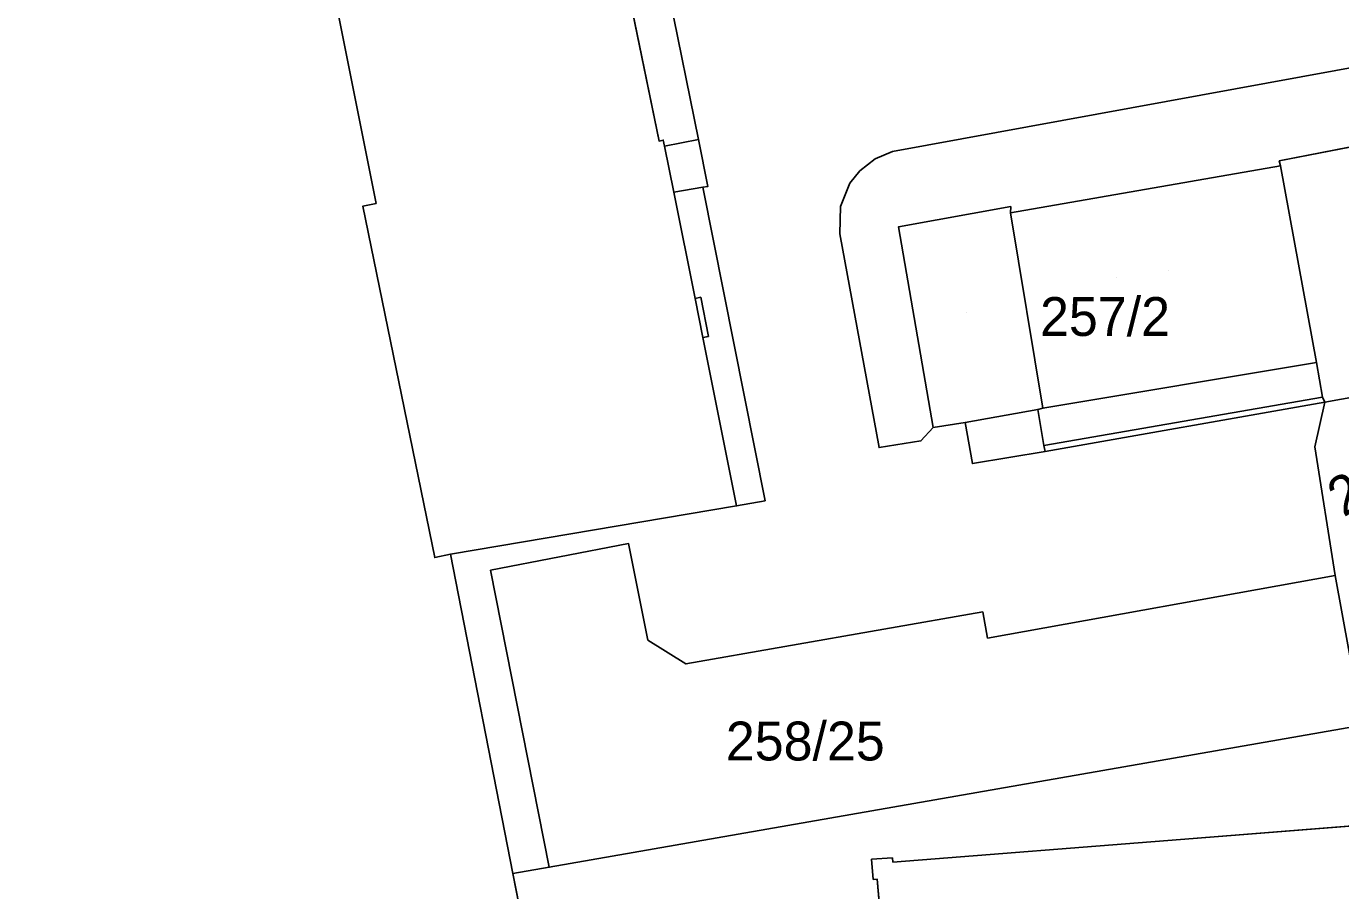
# Model space of a CAD drawing. Extents: x -263423 to -261326, y -1240067 to -1237864.
# Drawn here: x -263422.7 to -263355, y -1239493.9 to -1239449.5 of the extents above; entities that cross this region are included whole.
import ezdxf

# ---------------------------------------------------------------- set-up
doc = ezdxf.new("R2010")
doc.units = 0
for name, color, linetype in [('body_kn', 7, 'Continuous'), ('katuz_linie', 7, 'Continuous'), ('kladpar_druhypozemkov', 7, 'Continuous'), ('kladpar_hranice', 7, 'Continuous'), ('kladpar_parcelnecisla', 7, 'Continuous'), ('kladpar_plochy', 7, 'Continuous'), ('linie', 7, 'Continuous'), ('zappar_hrandruhpozemk', 7, 'Continuous'), ('znacky', 7, 'Continuous'), ('zuob_linie', 7, 'Continuous'), ('zuob_plochy', 7, 'Continuous')]:
    doc.layers.add(name, color=color, linetype=linetype)

msp = doc.modelspace()

# ---------------------------------------------------------------- linework, layer by layer
at = {"layer": 'body_kn'}
for p, q in [((-263390.09, -1239455.38), (-263390.09, -1239455.38)), ((-263389.88, -1239455.33), (-263389.88, -1239455.33)), ((-263389.82, -1239455.64), (-263389.82, -1239455.64)), ((-263388.07, -1239455.31), (-263388.07, -1239455.31)), ((-263378.96, -1239456.29), (-263378.96, -1239456.29)), ((-263378.08, -1239455.92), (-263378.08, -1239455.92)), ((-263358.16, -1239456.4), (-263358.16, -1239456.4)), ((-263379.75, -1239456.91), (-263379.75, -1239456.91)), ((-263358.1, -1239456.65), (-263358.1, -1239456.65)), ((-263358.1, -1239456.65), (-263358.1, -1239456.65)), ((-263387.84, -1239457.76), (-263387.84, -1239457.76)), ((-263387.84, -1239457.76), (-263387.84, -1239457.76)), ((-263387.58, -1239457.72), (-263387.58, -1239457.72)), ((-263380.27, -1239457.55), (-263380.27, -1239457.55)), ((-263404.66, -1239458.59), (-263404.66, -1239458.59)), ((-263389.34, -1239458.01), (-263389.34, -1239458.01)), ((-263389.34, -1239458.01), (-263389.34, -1239458.01)), ((-263405.35, -1239458.74), (-263405.35, -1239458.74)), ((-263380.75, -1239458.75), (-263380.75, -1239458.75)), ((-263372, -1239459.07), (-263372, -1239459.07)), ((-263372, -1239459.07), (-263372, -1239459.07)), ((-263371.99, -1239458.75), (-263371.99, -1239458.75)), ((-263377.77, -1239459.8), (-263377.77, -1239459.8)), ((-263380.78, -1239460.15), (-263380.78, -1239460.15)), ((-263388.24, -1239463.48), (-263388.24, -1239463.48)), ((-263387.95, -1239463.42), (-263387.95, -1239463.42)), ((-263387.84, -1239465.49), (-263387.84, -1239465.49)), ((-263387.84, -1239465.49), (-263387.84, -1239465.49)), ((-263387.55, -1239465.43), (-263387.55, -1239465.43)), ((-263356.25, -1239466.78), (-263356.25, -1239466.78)), ((-263356.25, -1239466.78), (-263356.25, -1239466.78)), ((-263355.94, -1239468.56), (-263355.94, -1239468.56)), ((-263355.94, -1239468.56), (-263355.94, -1239468.56)), ((-263370.59, -1239469.19), (-263370.59, -1239469.19)), ((-263370.33, -1239469.13), (-263370.33, -1239469.13)), ((-263370.33, -1239469.13), (-263370.33, -1239469.13)), ((-263355.82, -1239468.82), (-263355.82, -1239468.82)), ((-263374.33, -1239469.87), (-263374.33, -1239469.87)), ((-263374.33, -1239469.87), (-263374.33, -1239469.87)), ((-263375.98, -1239470.12), (-263375.98, -1239470.12)), ((-263378.77, -1239471.15), (-263378.77, -1239471.15)), ((-263376.61, -1239470.81), (-263376.61, -1239470.81)), ((-263370.28, -1239471.04), (-263370.28, -1239471.04)), ((-263370.22, -1239471.36), (-263370.22, -1239471.36)), ((-263356.33, -1239471.11), (-263356.33, -1239471.11)), ((-263373.96, -1239471.98), (-263373.96, -1239471.98)), ((-263386.1, -1239474.15), (-263386.1, -1239474.15)), ((-263384.63, -1239473.9), (-263384.63, -1239473.9)), ((-263391.66, -1239476.09), (-263391.66, -1239476.09)), ((-263401.64, -1239476.81), (-263401.64, -1239476.81)), ((-263400.83, -1239476.63), (-263400.83, -1239476.63)), ((-263398.77, -1239477.46), (-263398.77, -1239477.46)), ((-263355.29, -1239477.73), (-263355.29, -1239477.73)), ((-263373.43, -1239479.61), (-263373.43, -1239479.61)), ((-263390.67, -1239481.06), (-263390.67, -1239481.06)), ((-263373.18, -1239480.95), (-263373.18, -1239480.95)), ((-263388.71, -1239482.28), (-263388.71, -1239482.28)), ((-263363.24, -1239491.32), (-263363.24, -1239491.32)), ((-263379.15, -1239492.33), (-263379.15, -1239492.33)), ((-263378.08, -1239492.26), (-263378.08, -1239492.26)), ((-263397.62, -1239493.07), (-263397.62, -1239493.07)), ((-263395.75, -1239492.74), (-263395.75, -1239492.74)), ((-263378.05, -1239492.48), (-263378.05, -1239492.48)), ((-263379.07, -1239493.37), (-263379.07, -1239493.37)), ((-263378.86, -1239493.36), (-263378.86, -1239493.36))]:
    msp.add_line(p, q, dxfattribs=at)
at = {"layer": 'katuz_linie'}
msp.add_lwpolyline([(-263379.33, -1239586.34), (-263383.02, -1239567.53), (-263388.7, -1239538.56), (-263389.91, -1239532.38), (-263397.62, -1239493.07), (-263400.83, -1239476.63), (-263401.64, -1239476.81), (-263405.35, -1239458.74), (-263404.66, -1239458.59), (-263418.09, -1239391.46), (-263418.77, -1239388.14), (-263418.82, -1239387.92), (-263419.23, -1239385.88), (-263421.34, -1239375.54), (-263421.9, -1239372.78), (-263421.92, -1239372.66), (-263422.15, -1239371.54), (-263422.63, -1239368.77), (-263422.67, -1239368.54), (-263422.53, -1239349.75), (-263421.06, -1239264.03)], dxfattribs=at)
at = {"layer": 'kladpar_druhypozemkov'}
for p, q in [((-263366.56, -1239462.41), (-263366.56, -1239462.41)), ((-263374.26, -1239464.22), (-263374.26, -1239464.22)), ((-263381.83, -1239485.6), (-263381.83, -1239485.6))]:
    msp.add_line(p, q, dxfattribs=at)
at = {"layer": 'kladpar_hranice'}
for points in [[(-263396.18, -1239425.85), (-263390.09, -1239455.38), (-263389.88, -1239455.33), (-263389.82, -1239455.64), (-263388.07, -1239455.31), (-263387.58, -1239457.72), (-263387.84, -1239457.76), (-263389.34, -1239458.01), (-263388.24, -1239463.48), (-263387.95, -1239463.42), (-263387.55, -1239465.43), (-263387.84, -1239465.49), (-263386.1, -1239474.15), (-263400.83, -1239476.63), (-263401.64, -1239476.81), (-263405.35, -1239458.74), (-263404.66, -1239458.59), (-263418.09, -1239391.46)], [(-263345.41, -1239453.92), (-263358.16, -1239456.4), (-263358.1, -1239456.65), (-263372, -1239459.07), (-263371.99, -1239458.75), (-263377.77, -1239459.8), (-263375.98, -1239470.12), (-263374.33, -1239469.87), (-263373.96, -1239471.98), (-263370.22, -1239471.36), (-263355.82, -1239468.82), (-263356.33, -1239471.11), (-263355.29, -1239477.73), (-263373.18, -1239480.95), (-263373.43, -1239479.61), (-263388.71, -1239482.28), (-263390.67, -1239481.06), (-263391.66, -1239476.09), (-263398.77, -1239477.46), (-263395.75, -1239492.74), (-263397.62, -1239493.07), (-263400.83, -1239476.63), (-263386.1, -1239474.15), (-263387.84, -1239465.49), (-263387.55, -1239465.43), (-263387.95, -1239463.42), (-263388.24, -1239463.48), (-263389.34, -1239458.01), (-263387.84, -1239457.76), (-263387.58, -1239457.72), (-263388.07, -1239455.31), (-263389.82, -1239455.64), (-263389.88, -1239455.33), (-263390.09, -1239455.38), (-263396.18, -1239425.85)], [(-263345.41, -1239453.92), (-263346.15, -1239450.09), (-263306.88, -1239443.09), (-263306.58, -1239444.63), (-263305.83, -1239448.66), (-263303.99, -1239459.58), (-263329.55, -1239464.11), (-263329.37, -1239465.32), (-263332.48, -1239465.94), (-263332.42, -1239466.38), (-263335.14, -1239466.88), (-263335.27, -1239466.43), (-263338.25, -1239466.93), (-263338.5, -1239465.72), (-263342.75, -1239466.46), (-263355.82, -1239468.82), (-263355.94, -1239468.56), (-263356.25, -1239466.78), (-263358.1, -1239456.65), (-263358.16, -1239456.4), (-263345.41, -1239453.92)], [(-263358.1, -1239456.65), (-263356.25, -1239466.78), (-263355.94, -1239468.56), (-263355.82, -1239468.82), (-263370.22, -1239471.36), (-263373.96, -1239471.98), (-263374.33, -1239469.87), (-263375.98, -1239470.12), (-263377.77, -1239459.8), (-263371.99, -1239458.75), (-263372, -1239459.07), (-263358.1, -1239456.65)], [(-263389.91, -1239532.38), (-263397.62, -1239493.07), (-263395.75, -1239492.74), (-263353.87, -1239485.43), (-263325.89, -1239479.84), (-263317.64, -1239478.22), (-263315.49, -1239477.79), (-263315.85, -1239475.77), (-263316.6, -1239471.55), (-263269.27, -1239463.69), (-263264.52, -1239462.82)], [(-263269.27, -1239463.69), (-263316.6, -1239471.55), (-263315.85, -1239475.77), (-263315.49, -1239477.79), (-263317.64, -1239478.22), (-263325.89, -1239479.84), (-263353.87, -1239485.43), (-263355.29, -1239477.73), (-263356.33, -1239471.11), (-263355.82, -1239468.82), (-263342.75, -1239466.46)], [(-263353.87, -1239485.43), (-263395.75, -1239492.74), (-263398.77, -1239477.46), (-263391.66, -1239476.09), (-263390.67, -1239481.06), (-263388.71, -1239482.28), (-263373.43, -1239479.61), (-263373.18, -1239480.95), (-263355.29, -1239477.73), (-263353.87, -1239485.43)], [(-263314.18, -1239507.56), (-263316.62, -1239484.13), (-263327.94, -1239485.31), (-263327.33, -1239490.87), (-263328.05, -1239490.95), (-263327.76, -1239493.49), (-263331.17, -1239493.82), (-263331.7, -1239488.83), (-263346.85, -1239490.02), (-263363.24, -1239491.32), (-263378.05, -1239492.48), (-263378.08, -1239492.26), (-263379.15, -1239492.33), (-263379.07, -1239493.37), (-263378.86, -1239493.36), (-263378.5, -1239497.54)], [(-263363.24, -1239491.32), (-263346.85, -1239490.02), (-263331.7, -1239488.83), (-263331.17, -1239493.82), (-263327.76, -1239493.49), (-263327.58, -1239495.01), (-263329.16, -1239495.18), (-263328.74, -1239499.31), (-263327.1, -1239499.14), (-263327.04, -1239499.68), (-263328.76, -1239499.85), (-263334.62, -1239500.33), (-263335.83, -1239501.02), (-263336.28, -1239502.03), (-263336.11, -1239503.13), (-263335.45, -1239503.9)], [(-263378.5, -1239497.54), (-263378.86, -1239493.36), (-263379.07, -1239493.37), (-263379.15, -1239492.33), (-263378.08, -1239492.26), (-263378.05, -1239492.48), (-263363.24, -1239491.32)]]:
    msp.add_lwpolyline(points, dxfattribs=at)
at = {"layer": 'kladpar_plochy'}
for p, q in [((-263404.66, -1239458.59), (-263418.09, -1239391.46)), ((-263390.09, -1239455.38), (-263396.18, -1239425.85)), ((-263396.18, -1239425.85), (-263390.09, -1239455.38)), ((-263345.41, -1239453.92), (-263358.16, -1239456.4)), ((-263389.88, -1239455.33), (-263390.09, -1239455.38)), ((-263390.09, -1239455.38), (-263389.88, -1239455.33)), ((-263389.82, -1239455.64), (-263389.88, -1239455.33)), ((-263389.88, -1239455.33), (-263389.82, -1239455.64)), ((-263388.07, -1239455.31), (-263389.82, -1239455.64)), ((-263389.82, -1239455.64), (-263388.07, -1239455.31)), ((-263387.58, -1239457.72), (-263388.07, -1239455.31)), ((-263388.07, -1239455.31), (-263387.58, -1239457.72)), ((-263358.16, -1239456.4), (-263358.1, -1239456.65)), ((-263358.1, -1239456.65), (-263372, -1239459.07)), ((-263389.34, -1239458.01), (-263387.84, -1239457.76)), ((-263387.84, -1239457.76), (-263389.34, -1239458.01)), ((-263387.84, -1239457.76), (-263387.58, -1239457.72)), ((-263387.58, -1239457.72), (-263387.84, -1239457.76)), ((-263405.35, -1239458.74), (-263404.66, -1239458.59)), ((-263388.24, -1239463.48), (-263389.34, -1239458.01)), ((-263389.34, -1239458.01), (-263388.24, -1239463.48)), ((-263401.64, -1239476.81), (-263405.35, -1239458.74)), ((-263371.99, -1239458.75), (-263377.77, -1239459.8)), ((-263372, -1239459.07), (-263371.99, -1239458.75)), ((-263377.77, -1239459.8), (-263375.98, -1239470.12)), ((-263387.95, -1239463.42), (-263388.24, -1239463.48)), ((-263388.24, -1239463.48), (-263387.95, -1239463.42)), ((-263387.55, -1239465.43), (-263387.95, -1239463.42)), ((-263387.95, -1239463.42), (-263387.55, -1239465.43)), ((-263387.84, -1239465.49), (-263387.55, -1239465.43)), ((-263387.55, -1239465.43), (-263387.84, -1239465.49)), ((-263386.1, -1239474.15), (-263387.84, -1239465.49)), ((-263387.84, -1239465.49), (-263386.1, -1239474.15)), ((-263370.22, -1239471.36), (-263355.82, -1239468.82)), ((-263355.82, -1239468.82), (-263356.33, -1239471.11)), ((-263375.98, -1239470.12), (-263374.33, -1239469.87)), ((-263374.33, -1239469.87), (-263373.96, -1239471.98)), ((-263373.96, -1239471.98), (-263370.22, -1239471.36)), ((-263356.33, -1239471.11), (-263355.29, -1239477.73)), ((-263400.83, -1239476.63), (-263386.1, -1239474.15)), ((-263386.1, -1239474.15), (-263400.83, -1239476.63)), ((-263391.66, -1239476.09), (-263398.77, -1239477.46)), ((-263390.67, -1239481.06), (-263391.66, -1239476.09)), ((-263400.83, -1239476.63), (-263401.64, -1239476.81)), ((-263397.62, -1239493.07), (-263400.83, -1239476.63)), ((-263398.77, -1239477.46), (-263395.75, -1239492.74)), ((-263355.29, -1239477.73), (-263373.18, -1239480.95)), ((-263373.43, -1239479.61), (-263388.71, -1239482.28)), ((-263373.18, -1239480.95), (-263373.43, -1239479.61)), ((-263388.71, -1239482.28), (-263390.67, -1239481.06)), ((-263395.75, -1239492.74), (-263353.87, -1239485.43)), ((-263346.85, -1239490.02), (-263363.24, -1239491.32)), ((-263363.24, -1239491.32), (-263346.85, -1239490.02)), ((-263363.24, -1239491.32), (-263378.05, -1239492.48)), ((-263378.05, -1239492.48), (-263363.24, -1239491.32)), ((-263378.08, -1239492.26), (-263379.15, -1239492.33)), ((-263379.15, -1239492.33), (-263378.08, -1239492.26)), ((-263379.15, -1239492.33), (-263379.07, -1239493.37)), ((-263379.07, -1239493.37), (-263379.15, -1239492.33)), ((-263378.05, -1239492.48), (-263378.08, -1239492.26)), ((-263378.08, -1239492.26), (-263378.05, -1239492.48)), ((-263397.62, -1239493.07), (-263395.75, -1239492.74)), ((-263395.75, -1239492.74), (-263397.62, -1239493.07)), ((-263389.91, -1239532.38), (-263397.62, -1239493.07)), ((-263379.07, -1239493.37), (-263378.86, -1239493.36)), ((-263378.86, -1239493.36), (-263379.07, -1239493.37)), ((-263378.86, -1239493.36), (-263378.5, -1239497.54)), ((-263378.5, -1239497.54), (-263378.86, -1239493.36))]:
    msp.add_line(p, q, dxfattribs=at)
for points in [[(-263345.41, -1239453.92), (-263346.15, -1239450.09), (-263306.88, -1239443.09), (-263306.58, -1239444.63), (-263305.83, -1239448.66), (-263303.99, -1239459.58), (-263329.55, -1239464.11), (-263329.37, -1239465.32), (-263332.48, -1239465.94), (-263332.42, -1239466.38), (-263335.14, -1239466.88), (-263335.27, -1239466.43), (-263338.25, -1239466.93), (-263338.5, -1239465.72), (-263342.75, -1239466.46), (-263355.82, -1239468.82), (-263355.94, -1239468.56), (-263356.25, -1239466.78), (-263358.1, -1239456.65), (-263358.16, -1239456.4)], [(-263358.1, -1239456.65), (-263356.25, -1239466.78), (-263355.94, -1239468.56), (-263355.82, -1239468.82), (-263370.22, -1239471.36), (-263373.96, -1239471.98), (-263374.33, -1239469.87), (-263375.98, -1239470.12), (-263377.77, -1239459.8), (-263371.99, -1239458.75), (-263372, -1239459.07)], [(-263353.87, -1239485.43), (-263395.75, -1239492.74), (-263398.77, -1239477.46), (-263391.66, -1239476.09), (-263390.67, -1239481.06), (-263388.71, -1239482.28), (-263373.43, -1239479.61), (-263373.18, -1239480.95), (-263355.29, -1239477.73)]]:
    msp.add_lwpolyline(points, close=True, dxfattribs=at)
msp.add_lwpolyline([(-263353.87, -1239485.43), (-263355.29, -1239477.73), (-263356.33, -1239471.11), (-263355.82, -1239468.82), (-263342.75, -1239466.46)], dxfattribs=at)
at = {"layer": 'linie'}
msp.add_lwpolyline([(-263379.33, -1239586.34), (-263383.02, -1239567.53), (-263388.7, -1239538.56), (-263389.91, -1239532.38), (-263397.62, -1239493.07), (-263400.83, -1239476.63), (-263401.64, -1239476.81), (-263405.35, -1239458.74), (-263404.66, -1239458.59), (-263418.09, -1239391.46), (-263418.77, -1239388.14), (-263418.82, -1239387.92), (-263419.23, -1239385.88), (-263421.34, -1239375.54), (-263421.9, -1239372.78), (-263421.92, -1239372.66), (-263422.15, -1239371.54), (-263422.63, -1239368.77), (-263422.67, -1239368.54)], dxfattribs=at)
at = {"layer": 'zappar_hrandruhpozemk'}
for p, q in [((-263394.12, -1239425.43), (-263388.07, -1239455.31)), ((-263346.15, -1239450.09), (-263378.08, -1239455.92)), ((-263389.34, -1239458.01), (-263389.82, -1239455.64)), ((-263387.84, -1239457.76), (-263384.63, -1239473.9)), ((-263372, -1239459.07), (-263370.33, -1239469.13)), ((-263387.84, -1239465.49), (-263388.24, -1239463.48)), ((-263356.25, -1239466.78), (-263370.33, -1239469.13)), ((-263355.94, -1239468.56), (-263370.28, -1239471.04)), ((-263374.33, -1239469.87), (-263370.59, -1239469.19)), ((-263384.63, -1239473.9), (-263386.1, -1239474.15))]:
    msp.add_line(p, q, dxfattribs=at)
for points in [[(-263378.08, -1239455.92), (-263378.96, -1239456.29), (-263379.75, -1239456.91), (-263380.27, -1239457.55), (-263380.75, -1239458.75), (-263380.78, -1239460.15), (-263378.77, -1239471.15), (-263376.61, -1239470.81), (-263375.98, -1239470.12)], [(-263370.33, -1239469.13), (-263370.59, -1239469.19), (-263370.28, -1239471.04), (-263370.22, -1239471.36)]]:
    msp.add_lwpolyline(points, dxfattribs=at)
at = {"layer": 'znacky'}
msp.add_line((-263363.85, -1239462.03), (-263363.85, -1239462.03), dxfattribs=at)
at = {"layer": 'zuob_linie'}
msp.add_lwpolyline([(-263379.33, -1239586.34), (-263383.02, -1239567.53), (-263388.7, -1239538.56), (-263389.91, -1239532.38), (-263397.62, -1239493.07), (-263400.83, -1239476.63), (-263401.64, -1239476.81), (-263405.35, -1239458.74), (-263404.66, -1239458.59), (-263418.09, -1239391.46), (-263418.77, -1239388.14), (-263418.82, -1239387.92), (-263419.23, -1239385.88), (-263421.34, -1239375.54), (-263421.9, -1239372.78), (-263421.92, -1239372.66), (-263422.15, -1239371.54), (-263422.63, -1239368.77), (-263422.67, -1239368.54), (-263422.53, -1239349.75), (-263421.06, -1239264.03)], dxfattribs=at)
at = {"layer": 'zuob_plochy'}
msp.add_lwpolyline([(-263379.33, -1239586.34), (-263383.02, -1239567.53), (-263388.7, -1239538.56), (-263389.91, -1239532.38), (-263397.62, -1239493.07), (-263400.83, -1239476.63), (-263401.64, -1239476.81), (-263405.35, -1239458.74), (-263404.66, -1239458.59), (-263418.09, -1239391.46), (-263418.77, -1239388.14), (-263418.82, -1239387.92), (-263419.23, -1239385.88), (-263421.34, -1239375.54), (-263421.9, -1239372.78), (-263421.92, -1239372.66), (-263422.15, -1239371.54), (-263422.63, -1239368.77), (-263422.67, -1239368.54), (-263422.53, -1239349.75), (-263421.06, -1239264.03)], dxfattribs=at)

# ---------------------------------------------------------------- texts
at = {"layer": 'kladpar_parcelnecisla'}
for s, p in [('257/2', (-263370.48, -1239465.41)), ('258/25', (-263386.655, -1239487.25))]:
    msp.add_text(s, height=2, dxfattribs=at).set_placement(p)
msp.add_text('255/4', height=2, rotation=32, dxfattribs=at).set_placement((-263354.852, -1239474.763))

doc.saveas('drawing.dxf')
